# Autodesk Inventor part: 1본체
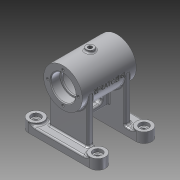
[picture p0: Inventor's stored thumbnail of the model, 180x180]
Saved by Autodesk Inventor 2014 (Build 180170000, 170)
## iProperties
Created: 2015-11
Part Number: 1본체
Material: 알루미늄 6061
Document SubType Name: Modeling
Designer: SEC
Density: 2.71 g/cm^3
Appearance: 알루미늄 - 평지
Mass: 359.113 g
Surface Area: 459.582 cm^2
Volume: 132.514 cm^3
Author: SEC
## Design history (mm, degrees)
sketch "스케치1"
  geometry: L1 (0, 10)-(80, 10); L2 (0, -10)-(80, -10); A1 r 10 centre (0, 0) between (0, 10) and (0, -10); A2 r 10 centre (80, 0) between (80, -10) and (80, 10); 1 further point
  constraints: 5 end point, 4 point on circle, 4 tangent, 2 centre point, 1 coincident, 1 horizontal alignment, 1 parallel
  dimensions: "d2" = 80 distance of L1.start L1.end; "d6" = 10 radius of A1
extrude "돌출1" new body sketch "스케치1" distance "d7" = 10; taper "d8" = 0 deg
node "작업 평면1"
sketch "스케치2"
  geometry: L1 (80, 0)-(0, 0) reference; L2 (80, 80)-(0, 80) reference; L3 (0, 60)-(80, 60) reference; C1 r 10 at (80, 10); C2 r 10 at (0, 10); A1 r 10 centre (80, 10) between (80, 0) and (80, 20) reference; A2 r 10 centre (0, 10) between (0, 20) and (0, 0) reference; A3 r 10 centre (0, 70) between (0, 80) and (0, 60) reference; A4 r 10 centre (80, 70) between (80, 60) and (80, 80) reference; 3 further points
  constraints: 4 coincident, 2 centre point, 2 vertical alignment, 1 concentric, 1 tangent, 4 other
extrude "돌출2" join sketch "스케치2" distance "d10" = 3; taper "d11" = 0 deg
node "작업 평면2"
sketch "스케치3"
  geometry: L1 (-50, 13)-(-70, 13) reference; L2 (-70, 0)-(-50, 0) reference; L3 (-70, 0)-(-70, 10) reference; L4 (-50, 10)-(-70, 10) reference; L5 (-50, 0)-(-50, 10) reference; L6 (10, 13)-(-10, 13) reference; L7 (10, 0)-(-10, 0) reference; L8 (-10, 0)-(-10, 10) reference; L9 (10, 10)-(-10, 10) reference; L10 (10, 0)-(10, 10) reference; L11 (-65, 68)-(5, 68); L12 (-65, 84)-(-65, 93); L13 (-65, 93)-(5, 93); L14 (5, 93)-(5, 84); L15 (-65, 84)-(-53, 84); L16 (-53, 84)-(-53, 82); L17 (-53, 82)-(-51, 82); L18 (-51, 82)-(-51, 89); L19 (-51, 89)-(-9, 89); L20 (-9, 89)-(-9, 82); L21 (-9, 82)-(-7, 82); L22 (-7, 82)-(-7, 84); L23 (-7, 84)-(5, 84); 1 further point
  constraints: 26 end point, 7 parallel, 6 perpendicular, 2 point on line, 1 collinear
  dimensions: "d13" = 70 distance of L11.start L11.end; "d14" = 68 distance from line of L7 L11.end; "d15" = 5 distance from line of L11.start L3; "d16" = 32 diameter of L23 L11; "d17" = 28 diameter of L21 L11; "d18" = 42 diameter of L19 L11; "d19" = 28 diameter of L17 L11; "d20" = 32 diameter of L15 L11; "d21" = 50 diameter of L13 L11; "d22" = 42 distance of L18.end L19.end; "d23" = 12 distance of L22.end L14.end; "d24" = 12 distance of L12.start L15.end
revolve "회전1" sketch "스케치3" stored, may be unused: angle "d25" = 90 deg
sketch "스케치4"
  geometry: L1 (80, 60)-(0, 60) reference; L2 (0, 40)-(80, 40) reference; L3 (80, -20)-(0, -20) reference; L4 (0, 0)-(80, 0) reference; L5 (15, 40)-(65, 40); L6 (65, 40)-(65, 48); L7 (65, 48)-(15, 48); L8 (15, 48)-(15, 40); L9 (15, 0)-(65, 0); L10 (65, 0)-(65, -8); L11 (65, -8)-(15, -8); L12 (15, -8)-(15, 0); A1 r 10 centre (80, 50) between (80, 40) and (80, 60) reference; A2 r 10 centre (0, 50) between (0, 60) and (0, 40) reference; A3 r 10 centre (0, -10) between (0, 0) and (0, -20) reference; A4 r 10 centre (80, -10) between (80, -20) and (80, 0) reference; 1 further point
  constraints: 16 end point, 4 parallel, 2 horizontal, 2 perpendicular, 2 point on line, 1 collinear
  dimensions: "d26" = 8 distance of L5.end L6.end; "d27" = 8 distance of L9.end L10.end; "d28" = 50 distance of L6.end L7.end; "d29" = 50 distance of L10.end L11.end; "d30" = 15 distance from line of L8 point (0, 50)
extrude "돌출3" join sketch "스케치4" stored distance "d31" = 3; taper "d32" = 0 deg
node "작업 평면3"
sketch "스케치5"
  geometry: L1 (65, 75)-(15, 75) reference; L2 (65, 12)-(65, 20) reference; L3 (65, 12)-(15, 12) reference; L4 (15, 12)-(15, 20) reference; L5 (15, 20)-(65, 20) reference; L6 (65, 5)-(15, 5) reference; L7 (65, 60)-(65, 68) reference; L8 (65, 60)-(15, 60) reference; L9 (15, 60)-(15, 68) reference; L10 (15, 68)-(65, 68) reference; L11 (44, 12)-(36, 12); L12 (36, 12)-(36, 60); L13 (36, 60)-(44, 60); L14 (44, 60)-(44, 12); 1 further point
  constraints: 8 end point, 2 parallel, 2 point on line, 1 horizontal, 1 perpendicular
  dimensions: "d34" = 8 distance of L11.start L11.end; "d35" = 21 distance between parallel lines of L14 L2
extrude "돌출4" join sketch "스케치5" stored distance "d36" = 3; taper "d37" = 0 deg
sketch "스케치6"
  geometry: L1 (0, 40)-(0, 0) reference; L2 (-10, 12)-(-10, 28); L3 (-13.5, 12)-(-13.5, 28); L4 (-6.5, 28)-(-6.5, 12); L5 (23, 60)-(23, 40) reference; L6 (-20, -15)-(-70, -15) reference; A1 r 3.5 centre (-10, 12) between (-13.5, 12) and (-6.5, 12); A2 r 3.5 centre (-10, 28) between (-6.5, 28) and (-13.5, 28); 2 further points
  constraints: 8 end point, 4 point on circle, 4 tangent, 2 centre point, 2 parallel, 1 midpoint
  dimensions: "d38" = 3.5 radius of A2; "d39" = 33 distance from line of point (-10, 20) L5; "d40" = 23 dimension on A2 A1; "d41" = 35 distance from line of point (-10, 20) L6
extrude "돌출5" cut sketch "스케치6" stored distance "d42" = 3; taper "d43" = 0 deg
node "작업 평면4"
sketch "스케치7"
  geometry: L1 (-15, -65)-(-65, -65) reference; L2 (-36, -10)-(-36, -50) reference; L3 (-36, -50)-(-15, -50) reference; L4 (-15, -58)-(-15, -50) reference; L5 (-15, -58)-(-65, -58) reference; L6 (-65, -58)-(-65, -50) reference; L7 (-65, -50)-(-44, -50) reference; L8 (-44, -50)-(-44, -10) reference; L9 (-44, -10)-(-65, -10) reference; L10 (-65, -10)-(-65, -2) reference; L11 (-65, -2)-(-15, -2) reference; L12 (-15, -10)-(-15, -2) reference; L13 (-15, -10)-(-36, -10) reference; L14 (-15, 5)-(-65, 5) reference; C1 r 5 at (-40, -30); 3 further points
  constraints: 2 midpoint, 1 centre point, 1 horizontal alignment, 1 vertical alignment
  dimensions: "d45" = 10 diameter of C1
extrude "돌출6" join sketch "스케치7" stored distance "d46" = 3; taper "d47" = 0 deg
hole "구멍1" diameter "d50" = 5.188; stored, may be unused: countersink angle "d54" = 90 deg, drill point angle "d56" = 118 deg; dims "d48" = 10, "d49" = 10, "d51" = 6, "d52" = 4, "d53" = 2, "d55" = 8
node "작업 평면9"
  node "작업 평면8"
sketch "스케치9"
  geometry: L1 (-35, -25)-(-35, 25) reference; L2 (20, -8.875)-(-20, -8.875) reference; L3 (-20, -8.875)-(-20, 21.651) reference; L4 (-28, 21.651)-(-20, 21.651) reference; L5 (-28, 21.651)-(-28, -21.651) reference; L6 (-28, -21.651)-(-20, -21.651) reference; L7 (-20, -21.651)-(-20, -15.803) reference; L8 (-20, -15.803)-(20, -15.803) reference; L9 (20, -15.803)-(20, -21.651) reference; L10 (20, -21.651)-(28, -21.651) reference; L11 (28, -21.651)-(28, 21.651) reference; L12 (20, 21.651)-(28, 21.651) reference; L13 (20, 21.651)-(20, -8.875) reference; L14 (35, -25)-(35, 25) reference; L15 (-35, 25)-(35, 25) reference; C1 r 6 at (0, 0); 3 further points
  constraints: 1 centre point, 1 horizontal alignment, 1 midpoint, 1 vertical alignment, 1 other
  dimensions: "d60" = 12 diameter of C1
extrude "돌출7" join sketch "스케치9" stored distance "d61" = 3; taper "d62" = 0 deg
hole "구멍2" diameter "d65" = 5.188; stored, may be unused: countersink angle "d69" = 90 deg, drill point angle "d71" = 118 deg; dims "d63" = 10, "d64" = 10, "d66" = 6, "d67" = 4, "d68" = 2, "d70" = 8
hole "구멍3" diameter "d74" = 6; stored, may be unused: countersink angle "d78" = 90 deg, drill point angle "d80" = 118 deg; dims "d72" = 10, "d73" = 10, "d75" = 6, "d76" = 4, "d77" = 2, "d79" = 8
hole "구멍4" diameter "d83" = 6; stored, may be unused: countersink angle "d87" = 90 deg, drill point angle "d89" = 118 deg; dims "d81" = 10, "d82" = 10, "d84" = 6, "d85" = 4, "d86" = 2, "d88" = 8
hole "구멍5" diameter "d92" = 6; stored, may be unused: countersink angle "d96" = 90 deg, drill point angle "d98" = 118 deg; dims "d90" = 10, "d91" = 10, "d93" = 6, "d94" = 4, "d95" = 2, "d97" = 8
hole "구멍6" diameter "d101" = 6; stored, may be unused: countersink angle "d105" = 90 deg, drill point angle "d107" = 118 deg; dims "d99" = 10, "d100" = 10, "d102" = 6, "d103" = 4, "d104" = 2, "d106" = 8
sketch "스케치10"
  geometry: C1 r 3 at (0, 0) reference; C2 r 10 at (0, 0) reference; C3 r 6 at (0, 0); C4 r 3 at (-80, 0) reference; C5 r 10 at (-80, 0) reference; C6 r 3 at (0, 60) reference; C7 r 10 at (0, 60) reference; C8 r 6 at (0, 60); C9 r 6 at (-80, 60); C10 r 6 at (-80, 0); 1 further point
  constraints: 4 centre point, 4 coincident, 3 equal radius
  dimensions: "d108" = 12 diameter of C8
extrude "돌출8" cut sketch "스케치10" distance "d109" = 4; taper "d110" = 0 deg
node "작업 평면10"
sketch "스케치11"
  geometry: L1 (35, -25)-(35, 25) reference; L2 (40, -68)-(20, -68) reference; L3 (-35, 25)-(35, 25) reference; 3 further points
  constraints: 1 midpoint, 1 vertical alignment, 1 other
  dimensions: "d112" = 25 vertical distance of point (0, 0) L1.end
feature "엠보싱1" sketch "스케치11" dims "d113" = 0.5, "d114" = 0
sketch "스케치12" dims "d115" = 40
  geometry: C1 r 16 at (0, 0) reference; C2 r 25 at (0, 0) reference; 3 further points
  constraints: 2 vertical alignment, 1 coincident, 2 other
hole "구멍7" sketch "스케치12" at (0, 20) diameter "d116" = 3.242; stored, may be unused: countersink angle "d120" = 90 deg, drill point angle "d122" = 118 deg; dims "d117" = 8, "d118" = 4, "d119" = 2, "d121" = 10
node "작업 평면11"
chamfer "모따기1" distance "d127" = 1; stored, may be unused: second distance "d128" = 2, angle "d129" = 45 deg
fillet "모깎기1" dims "d130" = 0.3
fillet "모깎기2" dims "d131" = 3
fillet "모깎기3" dims "d132" = 0.3
chamfer "모따기2" distance "d133" = 1; stored, may be unused: second distance "d134" = 2, angle "d135" = 45 deg
fillet "모깎기4" dims "d136" = 2
fillet "모깎기5" dims "d137" = 2
fillet "모깎기6" dims "d138" = 2
fillet "모깎기7" dims "d139" = 2
fillet "모깎기8" dims "d140" = 2
fillet "모깎기9" dims "d141" = 2
fillet "모깎기10" dims "d142" = 2
fillet "모깎기11" dims "d143" = 2
fillet "모깎기13" dims "d145" = 2
fillet "모깎기15" dims "d147" = 2
fillet "모깎기16" dims "d148" = 2
fillet "모깎기17" dims "d149" = 2
node "솔리드1"
mirror "대칭1"
pattern_circular "원형 패턴1" dims angle "d124" = 360 deg
mirror "대칭2"
node "투영된 루프1"
node "투영된 루프2"
node "투영된 루프3"
node "투영된 루프4"
node "투영된 루프5"
node "투영된 루프6"
node "투영된 루프7"
node "작업 평면5"
node "작업 평면6"
node "작업 평면7"
node "투영된 루프9"
node "투영된 루프10"
node "투영된 루프11"
other parameters: "d33" = -23, "d44" = -96, "d57" = 25, "d58" = 60 deg, "d59" = -3, "d126" = -35
